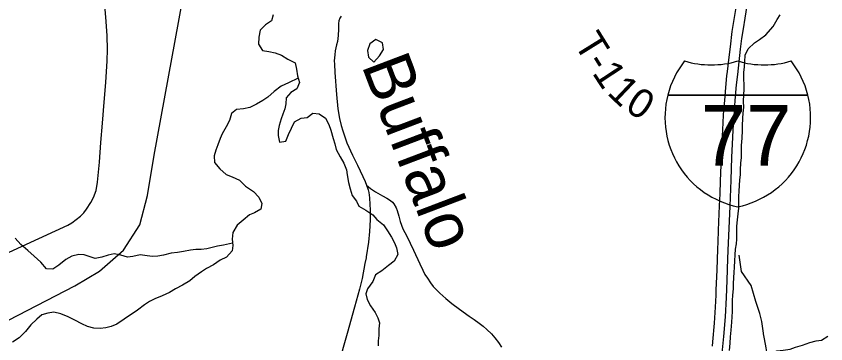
# Model space of a CAD drawing. Extents: x 0 to 34, y 0 to 22.
# Drawn here: x 6.508 to 8.087, y 18.632 to 19.271 of the extents above; entities that cross this region are included whole.
import ezdxf

# ---------------------------------------------------------------- set-up
doc = ezdxf.new("R2010")
doc.units = 0
for name, color, linetype in [('GM_X_County_Road', 7, 'Continuous'), ('GM_X_Interstate_Location', 7, 'Continuous'), ('GM_X_Interstate_Route', 7, 'Continuous'), ('GM_X_Interstate_Shield', 7, 'Continuous'), ('GM_X_Minor_Lake', 7, 'Continuous'), ('GM_X_Minor_River', 7, 'Continuous'), ('GM_X_Minor_River_Text', 7, 'Continuous'), ('GM_X_Rail_Line', 7, 'Continuous'), ('GM_X_State_Route', 7, 'Continuous'), ('GM_X_Township_Road', 7, 'Continuous'), ('GM_X_Township_Road_Text', 7, 'Continuous')]:
    doc.layers.add(name, color=color, linetype=linetype)

msp = doc.modelspace()

# ---------------------------------------------------------------- linework, layer by layer
at = {"layer": 'GM_X_County_Road'}
msp.add_lwpolyline([(7.1915, 18.9418), (7.1989, 18.9351), (7.209, 18.9288), (7.2226, 18.921), (7.2309, 18.9161), (7.238, 18.9117), (7.2418, 18.9085), (7.2443, 18.9055), (7.2492, 18.8977), (7.2512, 18.8923), (7.2544, 18.8813), (7.2569, 18.8707), (7.2624, 18.8567), (7.2699, 18.842), (7.2826, 18.8151), (7.295, 18.7886), (7.301, 18.7761), (7.305, 18.7678), (7.3099, 18.7604), (7.316, 18.7515), (7.3214, 18.7444), (7.3277, 18.7376), (7.3342, 18.7312), (7.3462, 18.7208), (7.3578, 18.7113), (7.3727, 18.6999), (7.3916, 18.6865), (7.4011, 18.68), (7.4107, 18.6729), (7.4186, 18.6666), (7.4259, 18.6605), (7.4349, 18.6516), (7.4415, 18.6441), (7.4484, 18.6349), (7.4547, 18.6259)], dxfattribs=at)
at = {"layer": 'GM_X_Interstate_Route'}
for points in [[(7.8849, 18.614), (7.8885, 18.6464), (7.8913, 18.6849), (7.8936, 18.7229), (7.8947, 18.7558), (7.8956, 18.7773), (7.8962, 18.7989), (7.8975, 18.8291), (7.8985, 18.8569), (7.9003, 18.9008), (7.9017, 18.9346), (7.9024, 18.9511), (7.9041, 18.996), (7.9058, 19.0343), (7.9065, 19.0493), (7.9088, 19.0858), (7.9105, 19.1066), (7.913, 19.137), (7.9152, 19.1576), (7.9206, 19.2064), (7.9235, 19.2276), (7.9264, 19.2462), (7.9295, 19.2671), (7.9348, 19.3001)], [(7.866, 18.628), (7.8668, 18.6362), (7.8701, 18.6725), (7.8722, 18.7039), (7.8731, 18.7273), (7.8735, 18.7372), (7.875, 18.7766), (7.8766, 18.8169), (7.8771, 18.8312), (7.8781, 18.8533), (7.8785, 18.87), (7.8799, 18.9016), (7.8809, 18.9245), (7.8819, 18.9502), (7.883, 18.9806), (7.884, 19.0018), (7.8845, 19.0183), (7.8861, 19.0482), (7.8869, 19.065), (7.8884, 19.0884), (7.8889, 19.0947), (7.8899, 19.1066), (7.892, 19.1321), (7.8943, 19.1546), (7.8951, 19.1629), (7.8984, 19.1909), (7.9009, 19.2113), (7.9047, 19.2409), (7.9076, 19.2604), (7.9133, 19.2954)]]:
    msp.add_lwpolyline(points, dxfattribs=at)
at = {"layer": 'GM_X_Interstate_Shield'}
for p, q in [((7.7788, 19.1172), (8.0521, 19.1172)), ((8.0521, 19.1172), (7.7788, 19.1172)), ((8.0521, 19.1172), (7.7788, 19.1172))]:
    msp.add_line(p, q, dxfattribs=at)
for centre, start, end in [((7.951, 19.0736), 141.669, 165.8066), ((7.8636, 19.3536), 253.0091, 286.9909), ((7.9673, 19.3536), 253.0091, 286.9909), ((7.8799, 19.0736), 14.1934, 38.331), ((7.951, 19.0736), 165.8066, 258.463), ((7.8799, 19.0736), 281.537, 14.1934)]:
    msp.add_arc(centre, 0.1776, start, end, dxfattribs=at)
at = {"layer": 'GM_X_Minor_Lake'}
for points in [[(7.2145, 19.223), (7.2094, 19.2256), (7.198, 19.2169), (7.1931, 19.204), (7.1949, 19.1911), (7.2055, 19.1816)], [(7.2055, 19.1816), (7.2169, 19.1938), (7.2245, 19.2059), (7.2222, 19.2191), (7.2145, 19.223)]]:
    msp.add_lwpolyline(points, dxfattribs=at)
at = {"layer": 'GM_X_Minor_River'}
for points in [[(7.0094, 19.2733), (7.006, 19.2619), (6.9943, 19.2539), (6.984, 19.2437), (6.981, 19.2301), (6.9806, 19.2164), (6.9881, 19.2043), (7.001, 19.202), (7.0134, 19.1997), (7.0255, 19.1952), (7.038, 19.1872), (7.052, 19.1803), (7.055, 19.1674), (7.0565, 19.1546), (7.0606, 19.1417), (7.0557, 19.1292), (7.0439, 19.1224), (7.0345, 19.1121), (7.0337, 19.1), (7.0318, 19.0902), (7.0283, 19.0803), (7.0245, 19.0708), (7.0211, 19.0576), (7.0192, 19.0481), (7.0192, 19.0382), (7.0218, 19.0254), (7.0339, 19.0276), (7.0389, 19.0405), (7.0449, 19.0526), (7.051, 19.0651), (7.0639, 19.0719), (7.0756, 19.0738), (7.0866, 19.0821), (7.0991, 19.0806), (7.1115, 19.0722), (7.1175, 19.0597), (7.1217, 19.0491), (7.1262, 19.0324), (7.1296, 19.0222), (7.1322, 19.0112), (7.1401, 18.9971), (7.1469, 18.9842), (7.1525, 18.9717), (7.1537, 18.9615), (7.1559, 18.9471), (7.1597, 18.9342), (7.163, 18.9217), (7.1717, 18.9103), (7.1766, 18.9008), (7.1898, 18.8928), (7.2038, 18.8841), (7.2117, 18.8746), (7.2242, 18.864), (7.2321, 18.8526), (7.24, 18.8405), (7.2457, 18.8291), (7.2498, 18.8192), (7.2521, 18.8063), (7.2452, 18.7935), (7.2343, 18.7848), (7.2214, 18.7745), (7.2085, 18.767), (7.2036, 18.7537), (7.1929, 18.7393), (7.1899, 18.7295), (7.1925, 18.7185), (7.1993, 18.7067), (7.208, 18.6934), (7.2133, 18.6828), (7.2163, 18.673), (7.2155, 18.6616), (7.2155, 18.6487), (7.2143, 18.6385), (7.2139, 18.6286)], [(7.9245, 19.048), (7.9245, 19.0575), (7.9253, 19.0719), (7.9261, 19.0817), (7.9269, 19.0938), (7.9265, 19.1048), (7.9273, 19.1181), (7.9277, 19.128), (7.9277, 19.1378), (7.927, 19.1484), (7.9274, 19.1609), (7.9285, 19.1723), (7.9293, 19.1822), (7.9301, 19.195), (7.9358, 19.2075), (7.9479, 19.2189), (7.9577, 19.2253), (7.9702, 19.2344), (7.9843, 19.2507), (7.9922, 19.2643), (7.9979, 19.2738)], [(7.0578, 19.1503), (7.0394, 19.1409), (7.025, 19.1345), (7.0114, 19.1243), (6.9989, 19.1133), (6.9891, 19.1069), (6.977, 19.0997), (6.9637, 19.0929), (6.9512, 19.0906), (6.938, 19.0891), (6.9281, 19.0816), (6.924, 19.0679), (6.9175, 19.0554), (6.9095, 19.0418), (6.9061, 19.0323), (6.9012, 19.0202), (6.8974, 19.0096), (6.8939, 18.9986), (6.8951, 18.9861), (6.9049, 18.9736), (6.9173, 18.9622), (6.929, 18.9576), (6.9434, 18.9512), (6.9551, 18.9398), (6.971, 18.9291), (6.9815, 18.9185), (6.9868, 18.906), (6.9853, 18.895), (6.9731, 18.8874), (6.9629, 18.8837), (6.9508, 18.8734), (6.9387, 18.8636), (6.9303, 18.8496), (6.9292, 18.8363), (6.9303, 18.8238), (6.9291, 18.8136), (6.9185, 18.8015), (6.906, 18.7954), (6.8928, 18.7863), (6.8792, 18.7792), (6.8693, 18.7724), (6.8564, 18.7637), (6.8466, 18.7549), (6.8326, 18.747), (6.819, 18.7398), (6.8072, 18.7326), (6.7925, 18.7258), (6.7785, 18.7202), (6.7682, 18.7149), (6.7584, 18.7084), (6.7444, 18.6978), (6.7183, 18.6804), (6.7043, 18.671), (6.6933, 18.6664), (6.6827, 18.6638), (6.6721, 18.6623), (6.6592, 18.6627), (6.6471, 18.6661), (6.6362, 18.6714), (6.6226, 18.6787), (6.6094, 18.6851), (6.595, 18.6908), (6.5814, 18.6939), (6.5697, 18.6924), (6.5583, 18.6886), (6.5481, 18.6807), (6.5367, 18.6697), (6.5265, 18.6564), (6.514, 18.6443), (6.5007, 18.6356)], [(7.8991, 18.6193), (7.9006, 18.6334), (7.9014, 18.6462), (7.9026, 18.6591), (7.9037, 18.6743), (7.9045, 18.6849), (7.9049, 18.6955), (7.905, 18.7171), (7.9057, 18.727), (7.9073, 18.7395), (7.9073, 18.749), (7.9077, 18.7618), (7.9085, 18.7713), (7.9089, 18.7819), (7.9096, 18.7941), (7.9104, 18.8058), (7.9112, 18.8172), (7.9131, 18.827), (7.9135, 18.8365), (7.9136, 18.8615), (7.9147, 18.874), (7.9163, 18.8858), (7.9174, 18.8971), (7.9175, 18.9195), (7.9178, 18.9297), (7.9186, 18.9411), (7.9194, 18.9517), (7.9206, 18.962), (7.921, 18.9722), (7.9214, 18.9847), (7.9225, 18.9953), (7.9229, 19.0052), (7.9229, 19.0188), (7.9237, 19.0332), (7.9245, 19.048)], [(6.9299, 18.8285), (6.9121, 18.8246), (6.9004, 18.8227), (6.8902, 18.8201), (6.88, 18.8178), (6.8686, 18.8163), (6.8584, 18.816), (6.8478, 18.8148), (6.8342, 18.8126), (6.8225, 18.8107), (6.8104, 18.8092), (6.7956, 18.8054), (6.7843, 18.8035), (6.7741, 18.8028), (6.7635, 18.8036), (6.7495, 18.8059), (6.7355, 18.8025), (6.7253, 18.801), (6.7124, 18.8055), (6.6992, 18.8078), (6.6871, 18.8052), (6.675, 18.8014), (6.6621, 18.7984), (6.6406, 18.8056), (6.6304, 18.8064), (6.6168, 18.803), (6.6047, 18.7969), (6.591, 18.786), (6.5797, 18.7776), (6.5672, 18.7788), (6.5562, 18.7913), (6.543, 18.8035), (6.5306, 18.8141), (6.5174, 18.8259), (6.506, 18.838)], [(7.8944, 18.5352), (7.9129, 18.5348), (7.9269, 18.537), (7.9379, 18.5374), (7.9523, 18.54), (7.9651, 18.5431), (7.9776, 18.548), (7.9852, 18.5578), (7.9841, 18.5726), (7.9815, 18.5825), (7.9796, 18.5919), (7.9811, 18.6067), (7.9914, 18.6188), (8.0042, 18.6203), (8.0178, 18.6218), (8.0281, 18.6256), (8.0413, 18.6301), (8.0557, 18.6347), (8.0682, 18.638), (8.0788, 18.6392), (8.0909, 18.6475)]]:
    msp.add_lwpolyline(points, dxfattribs=at)
at = {"layer": 'GM_X_Rail_Line'}
msp.add_lwpolyline([(6.493, 18.6782), (6.6221, 18.7453), (6.6705, 18.7738), (6.7176, 18.815), (6.7494, 18.8646), (6.7644, 18.9218), (6.7771, 19.0004), (6.8804, 19.5638)], dxfattribs=at)
at = {"layer": 'GM_X_State_Route'}
for points in [[(6.4052, 18.7704), (6.5279, 18.8265), (6.6086, 18.8639), (6.6168, 18.8684), (6.6253, 18.8747), (6.6333, 18.8812), (6.6398, 18.8876), (6.6453, 18.8949), (6.6538, 18.9079), (6.6588, 18.9173), (6.6639, 18.931), (6.6666, 18.9477), (6.6705, 18.9866), (6.6734, 19.025), (6.6765, 19.0622), (6.6799, 19.1035), (6.6827, 19.1414), (6.6855, 19.1837), (6.6859, 19.2058), (6.6852, 19.2324), (6.6838, 19.2605), (6.6813, 19.2847)], [(7.1421, 19.2711), (7.1394, 19.267), (7.1374, 19.2618), (7.1364, 19.2568), (7.1364, 19.2456), (7.1361, 19.2331), (7.1344, 19.2217), (7.1328, 19.2152), (7.1304, 19.2032), (7.1295, 19.1958), (7.1285, 19.184), (7.1287, 19.1774), (7.1298, 19.1613), (7.1329, 19.1182), (7.1356, 19.0903), (7.1386, 19.0714), (7.1416, 19.058), (7.1448, 19.0474), (7.1528, 19.0244), (7.1641, 18.9999), (7.1736, 18.9805), (7.1844, 18.9583), (7.1887, 18.9485), (7.1915, 18.9418), (7.1947, 18.9328), (7.1959, 18.927), (7.1972, 18.9167), (7.1978, 18.9038), (7.1983, 18.8934), (7.1982, 18.8742), (7.1974, 18.8512), (7.1953, 18.8306), (7.1907, 18.8022), (7.1903, 18.8002)], [(7.1903, 18.8002), (7.1881, 18.789), (7.1826, 18.76), (7.1775, 18.739), (7.1678, 18.7036), (7.1536, 18.6526), (7.1359, 18.591)]]:
    msp.add_lwpolyline(points, dxfattribs=at)
at = {"layer": 'GM_X_Township_Road'}
for points in [[(7.9655, 18.6531), (7.9625, 18.6757), (7.9586, 18.6914), (7.9509, 18.715), (7.9414, 18.7459), (7.9228, 18.7734), (7.9182, 18.8052)], [(7.8984, 18.2574), (7.9023, 18.2671), (7.905, 18.274), (7.9074, 18.2805), (7.9181, 18.3104), (7.9272, 18.3354), (7.938, 18.3661), (7.9516, 18.4039), (7.9595, 18.4248), (7.9678, 18.4456), (7.9804, 18.4753), (7.9847, 18.4873), (7.986, 18.4938), (7.9862, 18.5009), (7.9839, 18.5226), (7.9837, 18.5413), (7.9829, 18.5542), (7.9812, 18.569), (7.9777, 18.5888), (7.9735, 18.6087), (7.9707, 18.6247), (7.9677, 18.6423), (7.9657, 18.6521), (7.9655, 18.6531)]]:
    msp.add_lwpolyline(points, dxfattribs=at)

# ---------------------------------------------------------------- texts
at = {"layer": 'GM_X_Interstate_Location'}
for s in ['-', '.', ',']:
    msp.add_text(s, height=0.000189, dxfattribs=at).set_placement((7.9154, 19.0416))
msp.add_text('77', height=0.000189, rotation=0, dxfattribs=at).set_placement((7.8767, 19.0024))
at = {"layer": 'GM_X_Interstate_Shield'}
msp.add_text('77', height=0.11837, dxfattribs=at).set_placement((7.8436, 18.9796))
at = {"layer": 'GM_X_Minor_River_Text'}
msp.add_text('Buffalo', height=0.09468, rotation=290.7843, dxfattribs=at).set_placement((7.1809, 19.1756))
at = {"layer": 'GM_X_Township_Road_Text'}
for s, rotation, p in [('T', 301.776, (7.5946, 19.2176)), ('-', 301.9546, (7.6171, 19.1813)), ('1', 303.2897, (7.6302, 19.1603)), ('1', 316.4609, (7.6586, 19.1201)), ('0', 327.1668, (7.693, 19.0889))]:
    msp.add_text(s, height=0.0568, rotation=rotation, dxfattribs=at).set_placement(p)

doc.saveas('drawing.dxf')
